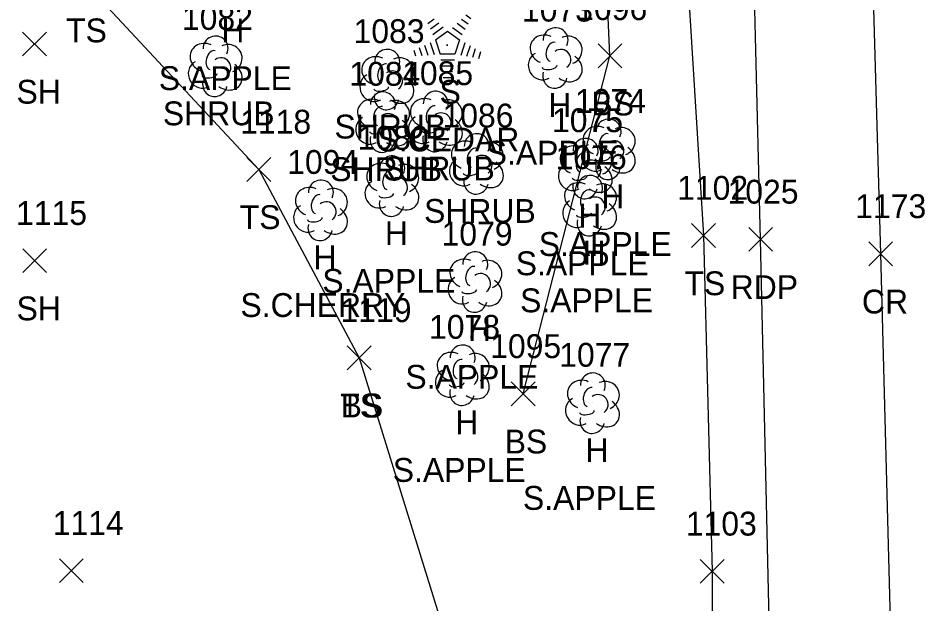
# Model space of a CAD drawing. Extents: x 1609623 to 1616187, y 756677 to 762826.
# Drawn here: x 1610553.8 to 1610629.1, y 761370.1 to 761419.2 of the extents above; entities that cross this region are included whole.
import ezdxf

# ---------------------------------------------------------------- set-up
doc = ezdxf.new("R2010")
doc.units = 0
for name, color, linetype in [('L_A', 7, 'Continuous'), ('L_C', 7, 'Continuous'), ('L_I', 7, 'Continuous'), ('L_TIC', 7, 'Continuous'), ('LELB', 7, 'Continuous'), ('LSH', 7, 'Continuous'), ('LTC', 7, 'Continuous'), ('LTD', 7, 'Continuous'), ('P_A', 7, 'Continuous'), ('P_I', 7, 'Continuous'), ('P_TIC', 7, 'Continuous'), ('PET', 7, 'Continuous'), ('PRC', 7, 'Continuous')]:
    doc.layers.add(name, color=color, linetype=linetype)

msp = doc.modelspace()

# ---------------------------------------------------------------- linework, layer by layer
at = {"layer": 'L_TIC'}
for points in [[(1610554.206, 761415.969), (1610556.206, 761417.969)], [(1610556.206, 761415.969), (1610554.206, 761417.969)], [(1610602.437, 761414.978), (1610604.437, 761416.978)], [(1610604.437, 761414.978), (1610602.437, 761416.978)], [(1610572.999, 761405.454), (1610574.999, 761407.454)], [(1610574.999, 761405.454), (1610572.999, 761407.454)], [(1610610.272, 761399.906), (1610612.272, 761401.906)], [(1610612.272, 761399.906), (1610610.272, 761401.906)], [(1610554.212, 761397.797), (1610556.212, 761399.797)], [(1610556.212, 761397.797), (1610554.212, 761399.797)], [(1610581.422, 761389.653), (1610583.422, 761391.653)], [(1610583.422, 761389.653), (1610581.422, 761391.653)], [(1610581.422, 761389.653), (1610583.422, 761391.653)], [(1610583.422, 761389.653), (1610581.422, 761391.653)], [(1610595.168, 761386.633), (1610597.168, 761388.633)], [(1610597.168, 761386.633), (1610595.168, 761388.633)], [(1610557.291, 761371.803), (1610559.291, 761373.803)], [(1610559.291, 761371.803), (1610557.291, 761373.803)], [(1610610.999, 761371.747), (1610612.999, 761373.747)], [(1610612.999, 761371.747), (1610610.999, 761373.747)]]:
    msp.add_lwpolyline(points, dxfattribs=at)
at = {"layer": 'LELB'}
for points in [[(1610595.408, 761447.245), (1610608.722, 761446.603), (1610609.524, 761429.323), (1610611.272, 761400.906), (1610611.999, 761372.747), (1610611.991, 761340.299), (1610612.489, 761301.493), (1610613.599, 761291.642), (1610617.432, 761248.111), (1610619.063, 761216.607), (1610613.007, 761244.85), (1610608.328, 761282.169), (1610599.672, 761300.772), (1610566.416, 761313.734)], [(1610596.168, 761387.633), (1610603.437, 761415.978), (1610602.455, 761438.458), (1610594.878, 761439.959), (1610595.408, 761447.245)], [(1610559.441, 761422.114), (1610573.999, 761406.454), (1610582.422, 761390.653)], [(1610582.422, 761390.653), (1610591.586, 761361.075), (1610598.212, 761322.877)]]:
    msp.add_lwpolyline(points, dxfattribs=at)
at = {"layer": 'LSH'}
for p, q in [((1610570.332, 761415.157), (1610570.332, 761415.157)), ((1610570.332, 761415.157), (1610570.332, 761415.157)), ((1610584.717, 761414.045), (1610584.717, 761414.045)), ((1610584.717, 761414.045), (1610584.717, 761414.045)), ((1610584.365, 761410.472), (1610584.365, 761410.472)), ((1610584.365, 761410.472), (1610584.365, 761410.472)), ((1610588.789, 761410.527), (1610588.789, 761410.527)), ((1610588.789, 761410.527), (1610588.789, 761410.527)), ((1610592.225, 761406.972), (1610592.225, 761406.972)), ((1610592.225, 761406.972), (1610592.225, 761406.972))]:
    msp.add_line(p, q, dxfattribs=at)
for centre in [(1610570.379, 761416.591), (1610584.764, 761415.479), (1610584.412, 761411.906), (1610588.835, 761411.961), (1610592.272, 761408.406)]:
    msp.add_arc(centre, 1.047, 335.52715, 180.95627, dxfattribs=at)
for centre, major_axis, ratio, start_param, end_param in [((1610569.54, 761415.824), (1.21, -0.512), 0.895232, 1.570796, 4.712389), ((1610570.124, 761415.616), (-0.208, -0.792), 0.645439, 3.141593, 6.283185), ((1610571.374, 761415.741), (-1.141, -0.483), 0.949671, 1.570796, 4.712389), ((1610570.832, 761414.991), (-0.5, 0.667), 0.989748, 3.141593, 6.283185), ((1610583.926, 761414.712), (1.21, -0.512), 0.895232, 1.570796, 4.712389), ((1610585.759, 761414.629), (-1.141, -0.483), 0.949671, 1.570796, 4.712389), ((1610569.249, 761414.449), (0.584, -1.042), 0.959034, 3.141593, 6.283185), ((1610571.332, 761414.324), (-1.09, 0.792), 0.841452, 1.570796, 4.712389), ((1610584.509, 761414.504), (-0.208, -0.792), 0.645439, 3.141593, 6.283185), ((1610569.874, 761414.407), (-0.625, -0.083), 0.423636, 0, 3.141593), ((1610583.634, 761413.337), (0.584, -1.042), 0.959034, 3.141593, 6.283185), ((1610585.218, 761413.879), (-0.5, 0.667), 0.989748, 3.141593, 6.283185), ((1610585.718, 761413.212), (-1.09, 0.792), 0.841452, 1.570796, 4.712389), ((1610570.332, 761413.657), (0.265, 1.061), 0.942809, 1.570796, 4.712389), ((1610584.259, 761413.295), (-0.625, -0.083), 0.423636, 0, 3.141593), ((1610584.718, 761412.545), (0.265, 1.061), 0.942809, 1.570796, 4.712389), ((1610583.573, 761411.138), (1.21, -0.512), 0.895232, 1.570796, 4.712389), ((1610585.407, 761411.055), (-1.141, -0.483), 0.949671, 1.570796, 4.712389), ((1610587.997, 761411.194), (1.21, -0.512), 0.895232, 1.570796, 4.712389), ((1610589.83, 761411.111), (-1.141, -0.483), 0.949671, 1.570796, 4.712389), ((1610584.157, 761410.93), (-0.208, -0.792), 0.645439, 3.141593, 6.283185), ((1610584.865, 761410.305), (-0.5, 0.667), 0.989748, 3.141593, 6.283185), ((1610588.58, 761410.985), (-0.208, -0.792), 0.645439, 3.141593, 6.283185), ((1610589.289, 761410.36), (-0.5, 0.667), 0.989748, 3.141593, 6.283185), ((1610583.282, 761409.763), (0.584, -1.042), 0.959034, 3.141593, 6.283185), ((1610585.365, 761409.638), (-1.09, 0.792), 0.841452, 1.570796, 4.712389), ((1610587.705, 761409.819), (0.584, -1.042), 0.959034, 3.141593, 6.283185), ((1610589.789, 761409.694), (-1.09, 0.792), 0.841452, 1.570796, 4.712389), ((1610583.907, 761409.722), (-0.625, -0.083), 0.423636, 0, 3.141593), ((1610588.33, 761409.777), (-0.625, -0.083), 0.423636, 0, 3.141593), ((1610584.365, 761408.972), (0.265, 1.061), 0.942809, 1.570796, 4.712389), ((1610588.789, 761409.027), (0.265, 1.061), 0.942809, 1.570796, 4.712389), ((1610591.434, 761407.639), (1.21, -0.512), 0.895232, 1.570796, 4.712389), ((1610593.267, 761407.556), (-1.141, -0.483), 0.949671, 1.570796, 4.712389), ((1610592.017, 761407.431), (-0.208, -0.792), 0.645439, 3.141593, 6.283185), ((1610592.725, 761406.806), (-0.5, 0.667), 0.989748, 3.141593, 6.283185), ((1610591.142, 761406.264), (0.584, -1.042), 0.959034, 3.141593, 6.283185), ((1610593.225, 761406.139), (-1.09, 0.792), 0.841452, 1.570796, 4.712389), ((1610591.767, 761406.222), (-0.625, -0.083), 0.423636, 0, 3.141593), ((1610592.226, 761405.472), (0.265, 1.061), 0.942809, 1.570796, 4.712389)]:
    msp.add_ellipse(centre, major_axis=major_axis, ratio=ratio, start_param=start_param, end_param=end_param, dxfattribs=at)
at = {"layer": 'LTC'}
for p, q in [((1610591.359, 761419.411), (1610591.778, 761419.107)), ((1610588.17, 761418.705), (1610588.7, 761419.09)), ((1610588.38, 761418.24), (1610589.084, 761418.751)), ((1610590.617, 761418.715), (1610591.296, 761418.221)), ((1610590.988, 761419.063), (1610591.538, 761418.664)), ((1610588.59, 761417.774), (1610589.468, 761418.412)), ((1610588.814, 761417.319), (1610589.826, 761418.053)), ((1610589.826, 761418.053), (1610590.823, 761417.328)), ((1610590.246, 761418.366), (1610591.055, 761417.778)), ((1610588.814, 761417.319), (1610589.201, 761416.125)), ((1610590.823, 761417.328), (1610590.432, 761416.125)), ((1610586.993, 761416.45), (1610587.145, 761415.982)), ((1610587.449, 761416.667), (1610587.66, 761416.015)), ((1610587.904, 761416.883), (1610588.175, 761416.048)), ((1610588.36, 761417.1), (1610588.69, 761416.08)), ((1610591.26, 761417.058), (1610590.923, 761416.018)), ((1610591.705, 761416.807), (1610591.418, 761415.923)), ((1610592.15, 761416.557), (1610591.913, 761415.828)), ((1610590.432, 761416.125), (1610589.201, 761416.125)), ((1610592.594, 761416.307), (1610592.407, 761415.733)), ((1610590.393, 761415.625), (1610589.249, 761415.625)), ((1610590.31, 761415.125), (1610589.321, 761415.125)), ((1610590.226, 761414.625), (1610589.394, 761414.625)), ((1610590.142, 761414.125), (1610589.467, 761414.125))]:
    msp.add_line(p, q, dxfattribs=at)
at = {"layer": 'LTD'}
for p, q in [((1610598.832, 761415.855), (1610598.832, 761415.855)), ((1610598.832, 761415.855), (1610598.832, 761415.855)), ((1610603.276, 761408.197), (1610603.276, 761408.197)), ((1610603.276, 761408.197), (1610603.276, 761408.197)), ((1610601.349, 761406.581), (1610601.349, 761406.581)), ((1610601.349, 761406.581), (1610601.349, 761406.581)), ((1610585.138, 761405.107), (1610585.138, 761405.107)), ((1610585.138, 761405.107), (1610585.138, 761405.107)), ((1610579.156, 761403.079), (1610579.156, 761403.079)), ((1610579.156, 761403.079), (1610579.156, 761403.079)), ((1610601.714, 761403.474), (1610601.714, 761403.474)), ((1610601.714, 761403.474), (1610601.714, 761403.474)), ((1610592.1, 761397.062), (1610592.1, 761397.062)), ((1610592.1, 761397.062), (1610592.1, 761397.062)), ((1610591.043, 761389.25), (1610591.043, 761389.25)), ((1610591.043, 761389.25), (1610591.043, 761389.25)), ((1610601.952, 761386.904), (1610601.952, 761386.904)), ((1610601.952, 761386.904), (1610601.952, 761386.904))]:
    msp.add_line(p, q, dxfattribs=at)
for centre in [(1610598.878, 761417.289), (1610603.323, 761409.631), (1610601.396, 761408.014), (1610585.185, 761406.541), (1610601.761, 761404.908), (1610579.203, 761404.513), (1610592.147, 761398.496), (1610591.09, 761390.684), (1610601.999, 761388.338)]:
    msp.add_arc(centre, 1.047, 335.52715, 180.95627, dxfattribs=at)
for centre, major_axis, ratio, start_param, end_param in [((1610598.04, 761416.522), (1.21, -0.512), 0.895232, 1.570796, 4.712389), ((1610598.623, 761416.314), (-0.208, -0.792), 0.645439, 3.141593, 6.283185), ((1610599.873, 761416.439), (-1.141, -0.483), 0.949671, 1.570796, 4.712389), ((1610599.332, 761415.689), (-0.5, 0.667), 0.989748, 3.141593, 6.283185), ((1610597.748, 761415.147), (0.584, -1.042), 0.959034, 3.141593, 6.283185), ((1610599.832, 761415.022), (-1.09, 0.792), 0.841452, 1.570796, 4.712389), ((1610598.373, 761415.105), (-0.625, -0.083), 0.423636, 0, 3.141593), ((1610598.832, 761414.355), (0.265, 1.061), 0.942809, 1.570796, 4.712389), ((1610602.484, 761408.863), (1.21, -0.512), 0.895232, 1.570796, 4.712389), ((1610604.318, 761408.78), (-1.141, -0.483), 0.949671, 1.570796, 4.712389), ((1610603.068, 761408.655), (-0.208, -0.792), 0.645439, 3.141593, 6.283185), ((1610603.776, 761408.03), (-0.5, 0.667), 0.989748, 3.141593, 6.283185), ((1610600.558, 761407.247), (1.21, -0.512), 0.895232, 1.570796, 4.712389), ((1610602.193, 761407.488), (0.584, -1.042), 0.959034, 3.141593, 6.283185), ((1610602.391, 761407.164), (-1.141, -0.483), 0.949671, 1.570796, 4.712389), ((1610604.276, 761407.364), (-1.09, 0.792), 0.841452, 1.570796, 4.712389), ((1610601.141, 761407.039), (-0.208, -0.792), 0.645439, 3.141593, 6.283185), ((1610601.849, 761406.414), (-0.5, 0.667), 0.989748, 3.141593, 6.283185), ((1610602.818, 761407.447), (-0.625, -0.083), 0.423636, 0, 3.141593), ((1610584.347, 761405.774), (1.21, -0.512), 0.895232, 1.570796, 4.712389), ((1610586.18, 761405.691), (-1.141, -0.483), 0.949671, 1.570796, 4.712389), ((1610600.266, 761405.872), (0.584, -1.042), 0.959034, 3.141593, 6.283185), ((1610602.349, 761405.747), (-1.09, 0.792), 0.841452, 1.570796, 4.712389), ((1610603.276, 761406.697), (0.265, 1.061), 0.942809, 1.570796, 4.712389), ((1610584.93, 761405.565), (-0.208, -0.792), 0.645439, 3.141593, 6.283185), ((1610585.638, 761404.941), (-0.5, 0.667), 0.989748, 3.141593, 6.283185), ((1610600.891, 761405.83), (-0.625, -0.083), 0.423636, 0, 3.141593), ((1610578.365, 761403.745), (1.21, -0.512), 0.895232, 1.570796, 4.712389), ((1610584.055, 761404.399), (0.584, -1.042), 0.959034, 3.141593, 6.283185), ((1610586.139, 761404.274), (-1.09, 0.792), 0.841452, 1.570796, 4.712389), ((1610600.923, 761404.141), (1.21, -0.512), 0.895232, 1.570796, 4.712389), ((1610601.35, 761405.081), (0.265, 1.061), 0.942809, 1.570796, 4.712389), ((1610602.756, 761404.058), (-1.141, -0.483), 0.949671, 1.570796, 4.712389), ((1610578.948, 761403.537), (-0.208, -0.792), 0.645439, 3.141593, 6.283185), ((1610580.198, 761403.662), (-1.141, -0.483), 0.949671, 1.570796, 4.712389), ((1610584.68, 761404.357), (-0.625, -0.083), 0.423636, 0, 3.141593), ((1610601.506, 761403.933), (-0.208, -0.792), 0.645439, 3.141593, 6.283185), ((1610579.656, 761402.912), (-0.5, 0.667), 0.989748, 3.141593, 6.283185), ((1610585.139, 761403.607), (0.265, 1.061), 0.942809, 1.570796, 4.712389), ((1610600.631, 761402.766), (0.584, -1.042), 0.959034, 3.141593, 6.283185), ((1610602.215, 761403.308), (-0.5, 0.667), 0.989748, 3.141593, 6.283185), ((1610578.073, 761402.37), (0.584, -1.042), 0.959034, 3.141593, 6.283185), ((1610580.157, 761402.246), (-1.09, 0.792), 0.841452, 1.570796, 4.712389), ((1610602.715, 761402.641), (-1.09, 0.792), 0.841452, 1.570796, 4.712389), ((1610578.698, 761402.329), (-0.625, -0.083), 0.423636, 0, 3.141593), ((1610601.715, 761401.974), (0.265, 1.061), 0.942809, 1.570796, 4.712389), ((1610601.256, 761402.724), (-0.625, -0.083), 0.423636, 0, 3.141593), ((1610579.157, 761401.579), (0.265, 1.061), 0.942809, 1.570796, 4.712389), ((1610591.309, 761397.728), (1.21, -0.512), 0.895232, 1.570796, 4.712389), ((1610591.892, 761397.52), (-0.208, -0.792), 0.645439, 3.141593, 6.283185), ((1610593.142, 761397.645), (-1.141, -0.483), 0.949671, 1.570796, 4.712389), ((1610592.6, 761396.895), (-0.5, 0.667), 0.989748, 3.141593, 6.283185), ((1610591.017, 761396.353), (0.584, -1.042), 0.959034, 3.141593, 6.283185), ((1610593.1, 761396.229), (-1.09, 0.792), 0.841452, 1.570796, 4.712389), ((1610591.642, 761396.312), (-0.625, -0.083), 0.423636, 0, 3.141593), ((1610592.101, 761395.562), (0.265, 1.061), 0.942809, 1.570796, 4.712389), ((1610590.251, 761389.916), (1.21, -0.512), 0.895232, 1.570796, 4.712389), ((1610592.084, 761389.833), (-1.141, -0.483), 0.949671, 1.570796, 4.712389), ((1610590.835, 761389.708), (-0.208, -0.792), 0.645439, 3.141593, 6.283185), ((1610589.96, 761388.541), (0.584, -1.042), 0.959034, 3.141593, 6.283185), ((1610591.543, 761389.083), (-0.5, 0.667), 0.989748, 3.141593, 6.283185), ((1610592.043, 761388.417), (-1.09, 0.792), 0.841452, 1.570796, 4.712389), ((1610590.585, 761388.5), (-0.625, -0.083), 0.423636, 0, 3.141593), ((1610601.161, 761387.571), (1.21, -0.512), 0.895232, 1.570796, 4.712389), ((1610602.994, 761387.488), (-1.141, -0.483), 0.949671, 1.570796, 4.712389), ((1610591.043, 761387.75), (0.265, 1.061), 0.942809, 1.570796, 4.712389), ((1610601.744, 761387.363), (-0.208, -0.792), 0.645439, 3.141593, 6.283185), ((1610600.869, 761386.196), (0.584, -1.042), 0.959034, 3.141593, 6.283185), ((1610602.452, 761386.738), (-0.5, 0.667), 0.989748, 3.141593, 6.283185), ((1610602.952, 761386.071), (-1.09, 0.792), 0.841452, 1.570796, 4.712389), ((1610601.953, 761385.404), (0.265, 1.061), 0.942809, 1.570796, 4.712389), ((1610601.494, 761386.154), (-0.625, -0.083), 0.423636, 0, 3.141593)]:
    msp.add_ellipse(centre, major_axis=major_axis, ratio=ratio, start_param=start_param, end_param=end_param, dxfattribs=at)
at = {"layer": 'P_TIC'}
for points in [[(1610615.065, 761399.586), (1610617.065, 761401.586)], [(1610617.065, 761399.586), (1610615.065, 761401.586)], [(1610625.12, 761398.371), (1610627.12, 761400.371)], [(1610627.12, 761398.371), (1610625.12, 761400.371)]]:
    msp.add_lwpolyline(points, dxfattribs=at)
at = {"layer": 'PET'}
msp.add_lwpolyline([(1610623.624, 761216.531), (1610618.72, 761291.922), (1610617.262, 761347.821), (1610616.065, 761400.586), (1610615.001, 761443.708), (1610614.378, 761469.339), (1610613.176, 761498.389)], dxfattribs=at)
at = {"layer": 'PRC'}
msp.add_lwpolyline([(1610615.344, 761821.258), (1610616.764, 761769.945), (1610617.486, 761726.015), (1610618.266, 761675.989), (1610618.81, 761645.854), (1610620.706, 761596.252), (1610622.201, 761543.733), (1610623.768, 761494.009), (1610624.803, 761445.349), (1610626.12, 761399.371), (1610627.458, 761348.429), (1610629.428, 761292.428), (1610633.696, 761219.48)], dxfattribs=at)

# ---------------------------------------------------------------- texts
at = {"layer": 'L_A'}
for s, p in [('TS', (1610557.851, 761417.114)), ('H', (1610570.866, 761417.109)), ('SH', (1610553.695, 761411.969)), ('S', (1610589.152, 761411.963)), ('H', (1610598.265, 761410.855)), ('BS', (1610601.878, 761410.978)), ('SHRUB', (1610565.962, 761410.157)), ('SHRUB', (1610580.347, 761409.045)), ('SHRUB', (1610579.995, 761405.472)), ('SHRUB', (1610584.419, 761405.527)), ('H', (1610602.709, 761403.197)), ('SHRUB', (1610587.855, 761401.972)), ('TS', (1610572.408, 761401.454)), ('H', (1610600.782, 761401.581)), ('H', (1610584.571, 761400.107)), ('H', (1610578.59, 761398.079)), ('H', (1610601.148, 761398.474)), ('TS', (1610609.681, 761395.906)), ('SH', (1610553.7, 761393.797)), ('H', (1610591.533, 761392.062)), ('TS', (1610580.831, 761385.653)), ('BS', (1610580.862, 761385.653)), ('H', (1610590.476, 761384.25)), ('BS', (1610594.609, 761382.633)), ('H', (1610601.385, 761381.904))]:
    msp.add_text(s, height=2, dxfattribs=at).set_placement(p)
at = {"layer": 'L_C'}
for s, p in [('S.APPLE', (1610565.622, 761413.109)), ('S.CEDAR', (1610583.947, 761407.963)), ('S.APPLE', (1610593.021, 761406.855)), ('S.APPLE', (1610597.465, 761399.197)), ('S.APPLE', (1610595.538, 761397.581)), ('S.APPLE', (1610579.327, 761396.107)), ('S.CHERRY', (1610572.464, 761394.079)), ('S.APPLE', (1610595.903, 761394.474)), ('S.APPLE', (1610586.289, 761388.062)), ('S.APPLE', (1610585.232, 761380.25)), ('S.APPLE', (1610596.141, 761377.904))]:
    msp.add_text(s, height=2, dxfattribs=at).set_placement(p)
at = {"layer": 'L_I'}
for s, p in [('1096', (1610600.61, 761418.978)), ('1082', (1610567.56, 761418.157)), ('1073', (1610596.06, 761418.855)), ('1083', (1610581.946, 761417.045)), ('1084', (1610581.593, 761413.472)), ('1085', (1610586.017, 761413.527)), ('1074', (1610600.505, 761411.197)), ('1086', (1610589.399, 761409.972)), ('1118', (1610572.44, 761409.454)), ('1075', (1610598.578, 761409.581)), ('1080', (1610582.28, 761408.107)), ('1094', (1610576.385, 761406.079)), ('1076', (1610598.888, 761406.474)), ('1102', (1610609.067, 761403.906)), ('1115', (1610553.653, 761401.797)), ('1079', (1610589.321, 761400.062)), ('1119', (1610580.855, 761393.653)), ('1119', (1610580.855, 761393.653)), ('1078', (1610588.271, 761392.25)), ('1095', (1610593.397, 761390.633)), ('1077', (1610599.181, 761389.904)), ('1114', (1610556.732, 761375.803)), ('1103', (1610609.794, 761375.747))]:
    msp.add_text(s, height=2, dxfattribs=at).set_placement(p)
at = {"layer": 'LTC'}
msp.add_text('.', height=1.037, rotation=270, dxfattribs=at).set_placement((1610589.708, 761417.067))
at = {"layer": 'P_A'}
for s, p in [('RDP', (1610613.553, 761395.586)), ('CR', (1610624.553, 761394.371))]:
    msp.add_text(s, height=2, dxfattribs=at).set_placement(p)
at = {"layer": 'P_I'}
for s, p in [('1025', (1610613.293, 761403.586)), ('1173', (1610623.994, 761402.371))]:
    msp.add_text(s, height=2, dxfattribs=at).set_placement(p)

doc.saveas('drawing.dxf')
